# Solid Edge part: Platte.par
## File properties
Sűrűség: 0,000 kg/m^3
Pontosság: 0,990
Author: bmolnar
Last saved by: bmolnar
Revision: 76
Username: bmolnar
Dokumentum tartalom típus: 0
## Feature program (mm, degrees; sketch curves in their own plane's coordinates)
base feature "unnamed BaseFeature 1"
thread "unnamed Thread 1"
thread "unnamed Thread 2"
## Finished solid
Body 1: solid body, 65 faces, 114 edges, 88 vertices.
  Faces by surface: plane 38, cylinder 12, cone 10, torus 5
  Edges by curve: line 60, circle 36, spline 18
Bounding box of the edges (mm; curved faces can reach further): 39.952 x 39.952 x 8.000, from (-19.9758, -19.9758, 54) to (19.9758, 19.9758, 62).
Cylindrical faces by radius (mm): R1.5 x2, R1.621 x2, R1.75 x2, R2.75 x2, R3.25 x2, R4.25 x1, R5.5 x1
Conical faces (half-angle, radius in mm at the cone's reference point): 45 deg R1.85 x2, 45 deg R1.871 x4, 45 deg R5.75 x1, 60 deg R0.7217 x2, 60 deg R0.866 x1
Toroidal faces (ring radius, tube radius in mm): R1.6 r0.1 x2, R2.45 r0.3 x2, R3.75 r0.5 x1
Planar faces by outward normal: +x 1, +y 4, +z 7, -x 1, -y 4, -z 5, oblique 16
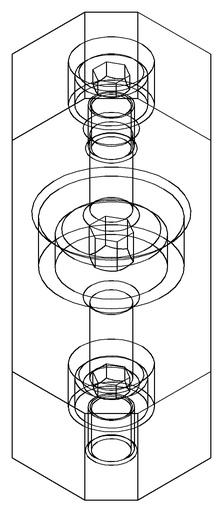
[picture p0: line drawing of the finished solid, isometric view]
